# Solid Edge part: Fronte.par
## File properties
Subject: FRONTE
Author: f_grande
Template: Normal.par
Last saved by: f_grande
Revision: 13
Application: Solid Edge
Densità: 750,000 kg/m^3
Precisione: 0,990
Tipo di contenuto documento: 0
Document Number: KR0105
Material: MDF
Stile della faccia: Marroncino
Coef. of Thermal Exp: 0.0
Thermal Conductivity: 0.0
Specific Heat: 0.0
Modulus of Elasticity: 0.0
Poisson's Ratio: 0.0
Yield Stress: 0.0
Ultimate Stress: 0.0
Elongation: 0.0
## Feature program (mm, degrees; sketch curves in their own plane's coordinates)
sketch for "unnamed Protrusion 1" plane through (0, 0, 0) normal (0, -1, 0) x-axis (1, 0, 0)
  line (0, 0) -> (850, 0)
  line (850, 0) -> (850, 190)
  line (850, 190) -> (780, 190)
  line (780, 190) -> (780, 160)
  line (70, 160) -> (780, 160)
  line (70, 190) -> (70, 160)
  line (0, 190) -> (70, 190)
  line (0, 0) -> (0, 190)
extrude "unnamed Protrusion 1" add finite 19 along +normal
fillet "Rotondo_1" radius 2
sketch for "ExtrudedCutout_1" #1 plane through (425, -19, 95) normal (0, -1, 0) x-axis (1, 0, 0)
  circle centre (305, -16) radius 12.5
sketch for "ExtrudedCutout_1" #2 plane through (425, -19, 95) normal (0, -1, 0) x-axis (1, 0, 0)
  circle centre (0, -20) radius 10
sketch for "ExtrudedCutout_1" #3 plane through (425, -19, 95) normal (0, -1, 0) x-axis (1, 0, 0)
  circle centre (-402.5, 72.5) radius 4.5
sketch for "ExtrudedCutout_1" #4 plane through (425, -19, 95) normal (0, -1, 0) x-axis (1, 0, 0)
  circle centre (-402.5, 22.6) radius 4.5
sketch for "ExtrudedCutout_1" #5 plane through (425, -19, 95) normal (0, -1, 0) x-axis (1, 0, 0)
  circle centre (-402.5, -22.5) radius 4.5
sketch for "ExtrudedCutout_1" #6 plane through (425, -19, 95) normal (0, -1, 0) x-axis (1, 0, 0)
  circle centre (-402.5, -72.4) radius 4.5
sketch for "ExtrudedCutout_1" #7 plane through (425, -19, 95) normal (0, -1, 0) x-axis (1, 0, 0)
  circle centre (402.5, 72.5) radius 4.5
sketch for "ExtrudedCutout_1" #8 plane through (425, -19, 95) normal (0, -1, 0) x-axis (1, 0, 0)
  circle centre (402.5, 22.6) radius 4.5
sketch for "ExtrudedCutout_1" #9 plane through (425, -19, 95) normal (0, -1, 0) x-axis (1, 0, 0)
  circle centre (402.5, -22.5) radius 4.5
sketch for "ExtrudedCutout_1" #10 plane through (425, -19, 95) normal (0, -1, 0) x-axis (1, 0, 0)
  circle centre (402.5, -72.4) radius 4.5
sketch for "ExtrudedCutout_1" #11 plane through (425, -19, 95) normal (0, -1, 0) x-axis (1, 0, 0)
  circle centre (-305, -16) radius 12.5
extrude "ExtrudedCutout_1" cut finite 19 along -normal
sketch for "Foro_7" plane through (425, -19, 95) normal (0, -1, 0) x-axis (1, 0, 0)
hole "Foro_7" diameter 5 through
sketch for "unnamed Hole 1" plane through (425, -19, 95) normal (0, -1, 0) x-axis (1, 0, 0)
  hole centre (0, 3.57) bore radius 2.5
hole "unnamed Hole 1" through
sketch for "unnamed Hole 2" plane through (425, -19, 95) normal (0, -1, 0) x-axis (1, 0, 0)
  hole centre (-23.57, -20) bore radius 2.5
hole "unnamed Hole 2" through
sketch for "unnamed Hole 3" plane through (425, -19, 95) normal (0, -1, 0) x-axis (1, 0, 0)
hole "unnamed Hole 3" through
pattern "unnamed Pattern 1" of "Foro_7", "unnamed Hole 1", "unnamed Hole 2", "unnamed Hole 3"
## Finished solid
Body 1: solid body, 29 faces, 66 edges, 24 vertices.
  Faces by surface: cylinder 19, plane 10
  Edges by curve: circle 38, line 28
Bounding box of the edges (mm): 850.000 x 19.000 x 190.000, from (0, -19, 0) to (850, 0, 190).
Cylindrical faces by radius (mm): R2 x4, R2.5 x4, R4.5 x8, R10 x1, R12.5 x2
Planar faces by outward normal: +x 2, +y 1, +z 3, -x 2, -y 1, -z 1
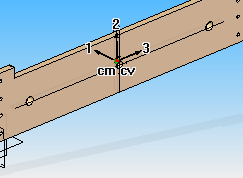
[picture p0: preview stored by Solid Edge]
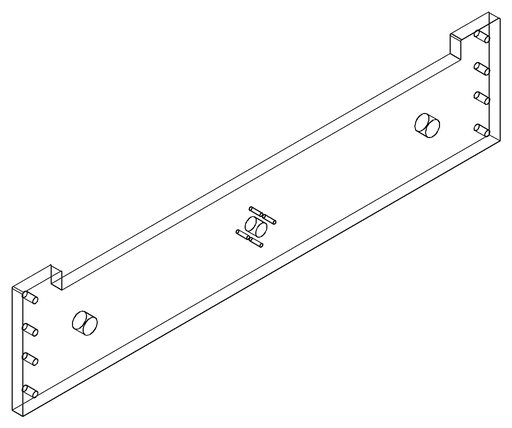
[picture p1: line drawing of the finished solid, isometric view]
